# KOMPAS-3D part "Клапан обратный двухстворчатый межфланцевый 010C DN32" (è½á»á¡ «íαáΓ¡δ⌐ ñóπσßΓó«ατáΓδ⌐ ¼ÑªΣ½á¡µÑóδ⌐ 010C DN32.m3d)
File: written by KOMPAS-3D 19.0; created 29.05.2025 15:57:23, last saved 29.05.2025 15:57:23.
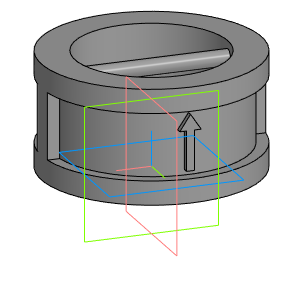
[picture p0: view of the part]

Document properties: Полное имя файла: E:\Dendor Работа Сачек\3D для проекитирвщиков\5.2 Тип 010C, 010C.Y Клапан обратный двухстворчатый межфланцевый\stp_Клапан обратный двухстворчатый межфланцевый 010C\Клапан обратный двухстворчатый межфланцевый 010C DN32.m3d

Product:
- Part/product: Клапан обратный двухстворчатый межфланцевый 010C DN32

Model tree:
1. Операция без истории:1  (labels: Клапан обратный двухстворчатый межфланцевый 010C DN32)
